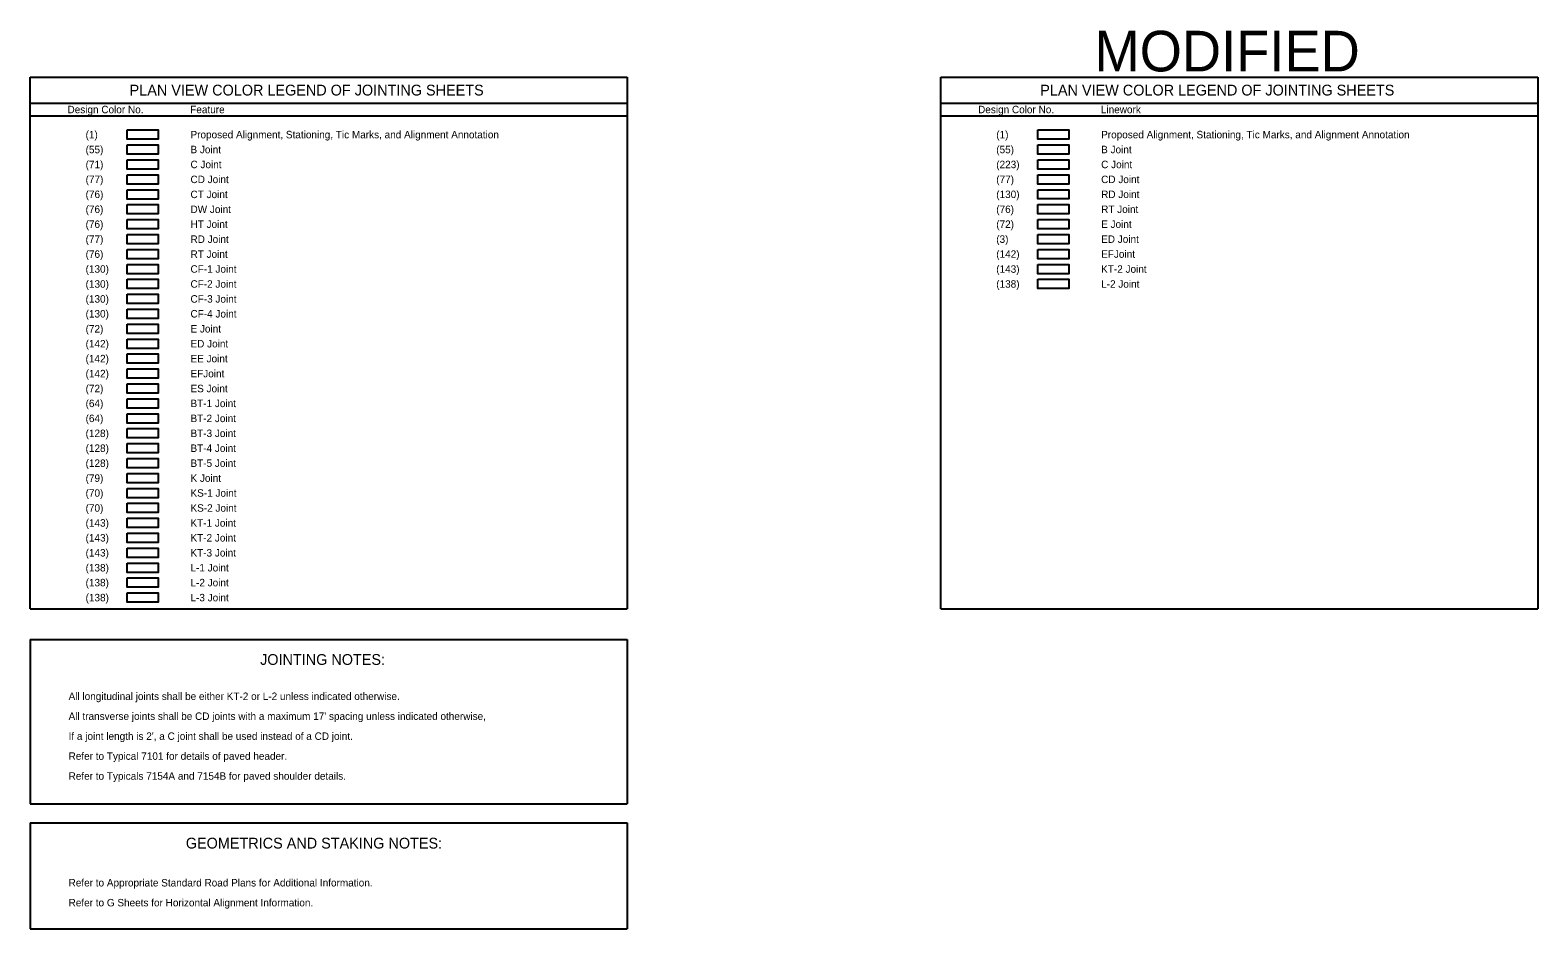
# Model space of a CAD drawing. Extents: x 5195678 to 5202789, y 3704048 to 3712766.
# Drawn here: x 5199758 to 5202789, y 3705896 to 3707701 of the extents above; entities that cross this region are included whole.
import ezdxf

# ---------------------------------------------------------------- set-up
doc = ezdxf.new("R2010")
doc.units = 0
for name, color, linetype in [('dsnAlignment', 7, 'Continuous'), ('dsnAlignmentCurveData', 7, 'Continuous'), ('dsnNonPlotable', 7, 'Continuous'), ('dsnXsExistingGround', 7, 'Continuous')]:
    doc.layers.add(name, color=color, linetype=linetype)

msp = doc.modelspace()

# ---------------------------------------------------------------- linework, layer by layer
at = {"layer": 'dsnAlignmentCurveData'}
for points in [[(5199953.2, 3707470.4), (5200015.7, 3707470.4), (5200015.7, 3707451.6), (5199953.2, 3707451.6)], [(5201783.4, 3707470.4), (5201845.9, 3707470.4), (5201845.9, 3707451.6), (5201783.4, 3707451.6)], [(5199953.2, 3707440.4), (5200015.7, 3707440.4), (5200015.7, 3707421.6), (5199953.2, 3707421.6)], [(5201783.4, 3707440.4), (5201845.9, 3707440.4), (5201845.9, 3707421.6), (5201783.4, 3707421.6)], [(5199953.2, 3707410.3), (5200015.7, 3707410.3), (5200015.7, 3707391.6), (5199953.2, 3707391.6)], [(5201783.4, 3707410.3), (5201845.9, 3707410.3), (5201845.9, 3707391.6), (5201783.4, 3707391.6)], [(5199953.2, 3707380.3), (5200015.7, 3707380.3), (5200015.7, 3707361.5), (5199953.2, 3707361.5)], [(5201783.4, 3707380.3), (5201845.9, 3707380.3), (5201845.9, 3707361.6), (5201783.4, 3707361.6)], [(5199953.2, 3707350.3), (5200015.7, 3707350.3), (5200015.7, 3707331.6), (5199953.2, 3707331.6)], [(5201783.4, 3707350.4), (5201845.9, 3707350.4), (5201845.9, 3707331.6), (5201783.4, 3707331.6)], [(5199953.2, 3707320.3), (5200015.7, 3707320.3), (5200015.7, 3707301.6), (5199953.2, 3707301.6)], [(5201783.4, 3707320.4), (5201845.9, 3707320.4), (5201845.9, 3707301.6), (5201783.4, 3707301.6)], [(5199953.2, 3707290.3), (5200015.7, 3707290.3), (5200015.7, 3707271.5), (5199953.2, 3707271.5)], [(5201783.4, 3707290.4), (5201845.9, 3707290.4), (5201845.9, 3707271.6), (5201783.4, 3707271.6)], [(5199953.2, 3707260.3), (5200015.7, 3707260.3), (5200015.7, 3707241.6), (5199953.2, 3707241.6)], [(5201783.4, 3707260.3), (5201845.9, 3707260.3), (5201845.9, 3707241.6), (5201783.4, 3707241.6)], [(5199953.2, 3707230.3), (5200015.7, 3707230.3), (5200015.7, 3707211.6), (5199953.2, 3707211.6)], [(5201783.4, 3707230.3), (5201845.9, 3707230.3), (5201845.9, 3707211.5), (5201783.4, 3707211.5)], [(5199953.2, 3707200.3), (5200015.7, 3707200.3), (5200015.7, 3707181.5), (5199953.2, 3707181.5)], [(5201783.4, 3707200.3), (5201845.9, 3707200.3), (5201845.9, 3707181.6), (5201783.4, 3707181.6)], [(5199953.2, 3707170.3), (5200015.7, 3707170.3), (5200015.7, 3707151.6), (5199953.2, 3707151.6)], [(5199953.2, 3707140.3), (5200015.7, 3707140.3), (5200015.7, 3707121.6), (5199953.2, 3707121.6)], [(5199953.2, 3707110.3), (5200015.7, 3707110.3), (5200015.7, 3707091.5), (5199953.2, 3707091.5)], [(5199953.2, 3707080.3), (5200015.7, 3707080.3), (5200015.7, 3707061.6), (5199953.2, 3707061.6)], [(5199953.2, 3707050.3), (5200015.7, 3707050.3), (5200015.7, 3707031.6), (5199953.2, 3707031.6)], [(5199953.2, 3707020.3), (5200015.7, 3707020.3), (5200015.7, 3707001.5), (5199953.2, 3707001.5)], [(5199953.2, 3706990.3), (5200015.7, 3706990.3), (5200015.7, 3706971.6), (5199953.2, 3706971.6)], [(5199953.2, 3706960.3), (5200015.7, 3706960.3), (5200015.7, 3706941.6), (5199953.2, 3706941.6)], [(5199953.2, 3706930.3), (5200015.7, 3706930.3), (5200015.7, 3706911.5), (5199953.2, 3706911.5)], [(5199953.2, 3706900.3), (5200015.7, 3706900.3), (5200015.7, 3706881.6), (5199953.2, 3706881.6)], [(5199953.2, 3706870.3), (5200015.7, 3706870.3), (5200015.7, 3706851.6), (5199953.2, 3706851.6)], [(5199953.2, 3706840.3), (5200015.7, 3706840.3), (5200015.7, 3706821.5), (5199953.2, 3706821.5)], [(5199953.2, 3706810.3), (5200015.7, 3706810.3), (5200015.7, 3706791.6), (5199953.2, 3706791.6)], [(5199953.2, 3706780.3), (5200015.7, 3706780.3), (5200015.7, 3706761.6), (5199953.2, 3706761.6)], [(5199953.2, 3706750.3), (5200015.7, 3706750.3), (5200015.7, 3706731.5), (5199953.2, 3706731.5)], [(5199953.2, 3706720.3), (5200015.7, 3706720.3), (5200015.7, 3706701.6), (5199953.2, 3706701.6)], [(5199953.2, 3706690.3), (5200015.7, 3706690.3), (5200015.7, 3706671.6), (5199953.2, 3706671.6)], [(5199953.2, 3706660.3), (5200015.7, 3706660.3), (5200015.7, 3706641.5), (5199953.2, 3706641.5)], [(5199953.2, 3706630.3), (5200015.7, 3706630.3), (5200015.7, 3706611.6), (5199953.2, 3706611.6)], [(5199953.2, 3706600.3), (5200015.7, 3706600.3), (5200015.7, 3706581.6), (5199953.2, 3706581.6)], [(5199953.2, 3706570.3), (5200015.7, 3706570.3), (5200015.7, 3706551.5), (5199953.2, 3706551.5)]]:
    msp.add_lwpolyline(points, close=True, dxfattribs=at)
at = {"layer": 'dsnNonPlotable'}
for p, q in [((5199758.3, 3707606.4), (5200958.3, 3707606.4)), ((5199758.3, 3706538.5), (5199758.3, 3707606.4)), ((5200958.3, 3707606.4), (5200958.3, 3706538.5)), ((5201588.6, 3707606.4), (5202788.6, 3707606.4)), ((5201588.6, 3706538.5), (5201588.6, 3707606.4)), ((5202788.6, 3707606.4), (5202788.6, 3706538.5)), ((5199758.3, 3706538.5), (5200958.3, 3706538.5)), ((5201588.6, 3706538.5), (5202788.6, 3706538.5)), ((5199758.3, 3706476.9), (5200958.3, 3706476.9)), ((5199758.3, 3706476.9), (5199758.3, 3706146.9)), ((5200958.3, 3706476.9), (5200958.3, 3706146.9)), ((5199758.3, 3706146.9), (5200958.3, 3706146.9)), ((5199758.3, 3706108.1), (5200958.3, 3706108.1)), ((5199758.3, 3706108.1), (5199758.3, 3705895.5)), ((5200958.3, 3706108.1), (5200958.3, 3705895.5)), ((5199758.3, 3705895.5), (5200958.3, 3705895.5))]:
    msp.add_line(p, q, dxfattribs=at)
at = {"layer": 'dsnXsExistingGround'}
for p, q in [((5199758.3, 3707554.4), (5200958.3, 3707554.4)), ((5201588.6, 3707554.4), (5202788.6, 3707554.4)), ((5199758.3, 3707528.4), (5200958.3, 3707528.4)), ((5201588.6, 3707528.4), (5202788.6, 3707528.4))]:
    msp.add_line(p, q, dxfattribs=at)
for points in [[(5199953.2, 3707500.4), (5200015.7, 3707500.4), (5200015.7, 3707481.6), (5199953.2, 3707481.6)], [(5201783.4, 3707500.4), (5201845.9, 3707500.4), (5201845.9, 3707481.6), (5201783.4, 3707481.6)]]:
    msp.add_lwpolyline(points, close=True, dxfattribs=at)

# ---------------------------------------------------------------- texts
at = {"layer": 'dsnAlignment'}
for s, height, p in [('MODIFIED', 81.58, (5201897.5, 3707617.9)), ('PLAN VIEW COLOR LEGEND OF JOINTING SHEETS', 21.667, (5199958.3, 3707569.5)), ('PLAN VIEW COLOR LEGEND OF JOINTING SHEETS', 21.667, (5201788.6, 3707569.5)), ('Design Color No.', 15, (5199833.4, 3707533.9)), ('Feature ', 15, (5200080.1, 3707533.9)), ('Design Color No.', 15, (5201663.6, 3707533.9)), ('Linework', 15, (5201910.4, 3707533.9)), ('(1) ', 15, (5199869.8, 3707483.5)), ('Proposed Alignment, Stationing, Tic Marks, and Alignment Annotation ', 15, (5200080.6, 3707483.5)), ('(1) ', 15, (5201700.1, 3707483.5)), ('Proposed Alignment, Stationing, Tic Marks, and Alignment Annotation ', 15, (5201910.9, 3707483.5)), ('(55) ', 15, (5199869.8, 3707453.5)), ('B Joint', 15, (5200080.6, 3707453.5)), ('(55) ', 15, (5201700.1, 3707453.5)), ('B Joint', 15, (5201910.9, 3707453.5)), ('(71) ', 15, (5199869.8, 3707423.5)), ('C Joint', 15, (5200080.6, 3707423.5)), ('(223) ', 15, (5201700.1, 3707423.5)), ('C Joint', 15, (5201910.9, 3707423.5)), ('(77) ', 15, (5199869.8, 3707393.5)), ('CD Joint', 15, (5200080.6, 3707393.5)), ('(77) ', 15, (5201700.1, 3707393.5)), ('CD Joint', 15, (5201910.9, 3707393.5)), ('(76) ', 15, (5199869.8, 3707363.5)), ('CT Joint', 15, (5200080.6, 3707363.4)), ('(130) ', 15, (5201700.1, 3707363.5)), ('RD Joint', 15, (5201910.9, 3707363.5)), ('(76) ', 15, (5199869.8, 3707333.5)), ('DW Joint', 15, (5200080.6, 3707333.4)), ('(76) ', 15, (5201700.1, 3707333.5)), ('RT Joint', 15, (5201910.9, 3707333.5)), ('(76)', 15, (5199869.8, 3707303.5)), ('HT Joint', 15, (5200080.6, 3707303.5)), ('(72) ', 15, (5201700.1, 3707303.5)), ('E Joint', 15, (5201910.9, 3707303.5)), ('(77) ', 15, (5199869.8, 3707273.4)), ('RD Joint', 15, (5200080.6, 3707273.4)), ('(3) ', 15, (5201700.1, 3707273.5)), ('ED Joint', 15, (5201910.9, 3707273.5)), ('(76) ', 15, (5199869.8, 3707243.4)), ('RT Joint', 15, (5200080.6, 3707243.4)), ('(142) ', 15, (5201700.1, 3707243.5)), ('EFJoint', 15, (5201910.9, 3707243.5)), ('(130) ', 15, (5199869.8, 3707213.5)), ('CF-1 Joint', 15, (5200080.6, 3707213.5)), ('(143) ', 15, (5201700.1, 3707213.4)), ('KT-2 Joint', 15, (5201910.9, 3707213.4)), ('(130) ', 15, (5199869.8, 3707183.4)), ('CF-2 Joint', 15, (5200080.6, 3707183.4)), ('(138) ', 15, (5201700.1, 3707183.4)), ('L-2 Joint', 15, (5201910.9, 3707183.4)), ('(130) ', 15, (5199869.8, 3707153.4)), ('CF-3 Joint', 15, (5200080.6, 3707153.4)), ('(130) ', 15, (5199869.8, 3707123.5)), ('CF-4 Joint', 15, (5200080.6, 3707123.5)), ('(72) ', 15, (5199869.8, 3707093.4)), ('E Joint', 15, (5200080.6, 3707093.4)), ('(142) ', 15, (5199869.8, 3707063.4)), ('ED Joint', 15, (5200080.6, 3707063.4)), ('(142) ', 15, (5199869.8, 3707033.5)), ('EE Joint', 15, (5200080.6, 3707033.5)), ('(142) ', 15, (5199869.8, 3707003.4)), ('EFJoint', 15, (5200080.6, 3707003.4)), ('(72) ', 15, (5199869.8, 3706973.4)), ('ES Joint', 15, (5200080.6, 3706973.4)), ('(64) ', 15, (5199869.8, 3706943.5)), ('BT-1 Joint', 15, (5200080.6, 3706943.5)), ('(64) ', 15, (5199869.8, 3706913.4)), ('BT-2 Joint', 15, (5200080.6, 3706913.4)), ('(128) ', 15, (5199869.8, 3706883.4)), ('BT-3 Joint', 15, (5200080.6, 3706883.4)), ('(128) ', 15, (5199869.8, 3706853.5)), ('BT-4 Joint', 15, (5200080.6, 3706853.5)), ('(128) ', 15, (5199869.8, 3706823.4)), ('BT-5 Joint', 15, (5200080.6, 3706823.4)), ('(79) ', 15, (5199869.8, 3706793.4)), ('K Joint', 15, (5200080.6, 3706793.4)), ('(70) ', 15, (5199869.8, 3706763.5)), ('KS-1 Joint', 15, (5200080.6, 3706763.5)), ('(70) ', 15, (5199869.8, 3706733.4)), ('KS-2 Joint', 15, (5200080.6, 3706733.4)), ('(143) ', 15, (5199869.8, 3706703.4)), ('KT-1 Joint', 15, (5200080.6, 3706703.4)), ('(143) ', 15, (5199869.8, 3706673.5)), ('KT-2 Joint', 15, (5200080.6, 3706673.5)), ('(143) ', 15, (5199869.8, 3706643.4)), ('KT-3 Joint', 15, (5200080.6, 3706643.4)), ('(138) ', 15, (5199869.8, 3706613.4)), ('L-1 Joint', 15, (5200080.6, 3706613.4)), ('(138) ', 15, (5199869.8, 3706583.5)), ('L-2 Joint', 15, (5200080.6, 3706583.5)), ('(138) ', 15, (5199869.8, 3706553.4)), ('L-3 Joint', 15, (5200080.6, 3706553.4)), ('JOINTING NOTES:', 21.667, (5200220.5, 3706425.7)), ('All longitudinal joints shall be either KT-2 or L-2 unless indicated otherwise.', 15, (5199835.6, 3706355.2)), ("All transverse joints shall be CD joints with a maximum 17' spacing unless indicated otherwise,", 15, (5199835.6, 3706315.2)), ("If a joint length is 2', a C joint shall be used instead of a CD joint.", 15, (5199835.6, 3706275.1)), ('Refer to Typical 7101 for details of paved header.', 15, (5199835.6, 3706235)), ('Refer to Typicals 7154A and 7154B for paved shoulder details.', 15, (5199835.6, 3706195)), ('GEOMETRICS AND STAKING NOTES:', 21.667, (5200071.2, 3706056.8)), ('Refer to Appropriate Standard Road Plans for Additional Information.', 15, (5199835.6, 3705980.6)), ('Refer to G Sheets for Horizontal Alignment Information.', 15, (5199835.6, 3705940.6))]:
    msp.add_text(s, height=height, dxfattribs=at).set_placement(p)

doc.saveas('drawing.dxf')
